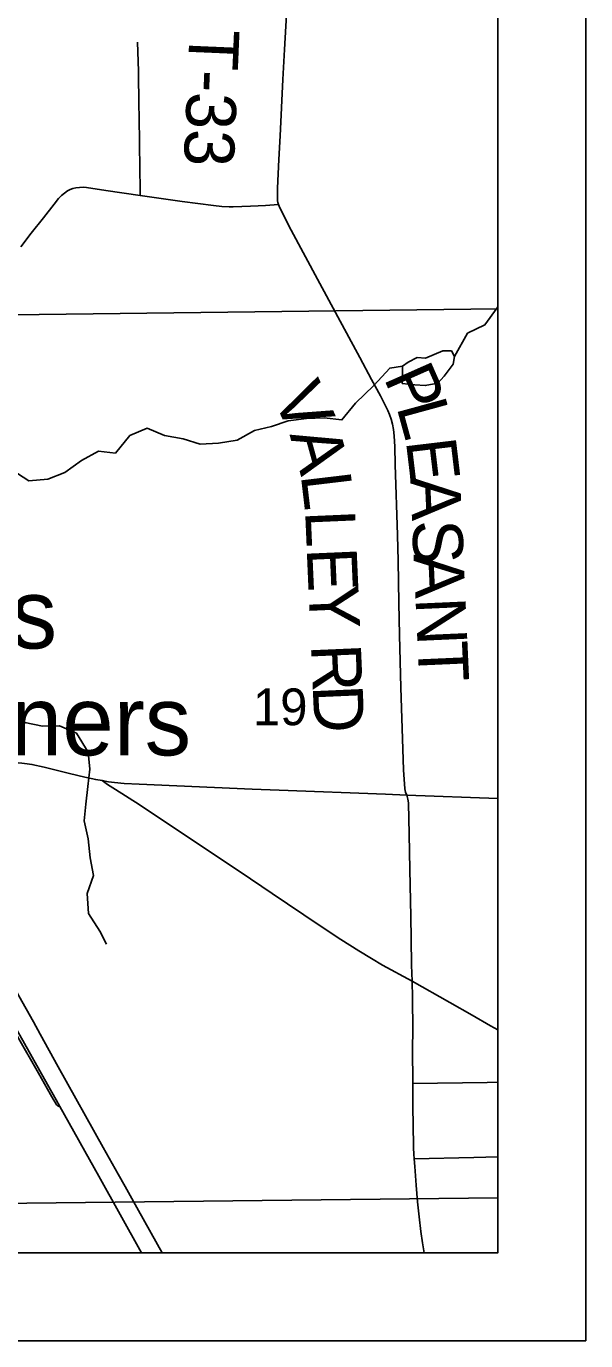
# Model space of a CAD drawing. Extents: x -6.4 to 34, y -4.2 to 22.
# Drawn here: x 8.363 to 9, y 14 to 15.496 of the extents above; entities that cross this region are included whole.
import ezdxf

# ---------------------------------------------------------------- set-up
doc = ezdxf.new("R2010")
doc.units = 0
for name, color, linetype in [('GM_X_Corporation', 7, 'Continuous'), ('GM_X_County_Road', 7, 'Continuous'), ('GM_X_Interchange_Ramps', 7, 'Continuous'), ('GM_X_Minor_Lake', 7, 'Continuous'), ('GM_X_Minor_River', 7, 'Continuous'), ('GM_X_Section_Text', 7, 'Continuous'), ('GM_X_State_Route', 7, 'Continuous'), ('GM_X_Township_Road', 7, 'Continuous'), ('GM_X_Township_Road_Text', 7, 'Continuous'), ('GM_X_Unincorporated_Text', 7, 'Continuous'), ('SH_Data', 7, 'Continuous')]:
    doc.layers.add(name, color=color, linetype=linetype)

msp = doc.modelspace()

# ---------------------------------------------------------------- linework, layer by layer
at = {"layer": 'GM_X_Corporation'}
for points in [[(8.9, 15.1746), (8.9, 15.9375), (8.744, 15.9349), (8.175, 15.9256), (8.0507, 15.9235), (8.0705, 15.1646)], [(7.1124, 14.1), (8.9, 14.1), (8.9, 15.9356), (8.6815, 15.9311), (7.2926, 15.9044), (7.2702, 15.904), (7.0636, 15.9014), (7.0744, 15.3393), (7.0897, 14.8536), (7.0948, 14.7153), (7.0983, 14.5939), (7.1017, 14.4646)], [(8.9, 14.1628), (8.9, 15.1746), (8.0705, 15.1646), (8.0954, 14.1535)], [(8.0976, 14.1), (8.9, 14.1), (8.9, 14.1628), (8.0954, 14.1535)]]:
    msp.add_lwpolyline(points, close=True, dxfattribs=at)
at = {"layer": 'GM_X_County_Road'}
for points in [[(8.3427, 14.6579), (8.3504, 14.658), (8.3544, 14.6579), (8.3583, 14.6575), (8.3646, 14.6568), (8.3698, 14.656), (8.3839, 14.6528), (8.4126, 14.6459), (8.4301, 14.6416), (8.4425, 14.6389), (8.4497, 14.6376), (8.457, 14.6363), (8.4638, 14.6354), (8.475, 14.6344), (8.4918, 14.6336), (8.6204, 14.6279), (8.6514, 14.6267), (8.7723, 14.6221)], [(8.7723, 14.6221), (8.7963, 14.6212), (8.9, 14.6174)]]:
    msp.add_lwpolyline(points, dxfattribs=at)
at = {"layer": 'GM_X_Interchange_Ramps'}
msp.add_lwpolyline([(8.3533, 14.3463), (8.3773, 14.3047), (8.391, 14.2803), (8.394, 14.2749), (8.3959, 14.2718), (8.3975, 14.2692), (8.398, 14.2686), (8.3989, 14.2677), (8.3994, 14.2673), (8.4003, 14.2669), (8.401, 14.2667), (8.4017, 14.2665)], dxfattribs=at)
at = {"layer": 'GM_X_Minor_Lake'}
msp.add_line((8.7915, 15.1022), (8.791, 15.0896), dxfattribs=at)
msp.add_lwpolyline([(8.791, 15.0896), (8.8054, 15.0881), (8.8175, 15.0873), (8.8319, 15.0902), (8.8388, 15.0982), (8.8491, 15.1118), (8.8506, 15.1205), (8.8473, 15.127), (8.8374, 15.127), (8.8177, 15.1184), (8.8082, 15.1192), (8.798, 15.1139), (8.7915, 15.1094), (8.7915, 15.1022)], dxfattribs=at)
at = {"layer": 'GM_X_Minor_River'}
for points in [[(8.8506, 15.1205), (8.8656, 15.147), (8.8853, 15.1564), (8.8994, 15.1757), (8.9, 15.1769)], [(8.3471, 14.9914), (8.3663, 14.9791), (8.3879, 14.9809), (8.4072, 14.9885), (8.4262, 15.002), (8.4456, 15.0126), (8.4649, 15.0106), (8.4813, 15.0307), (8.5011, 15.0389), (8.5207, 15.0305), (8.5419, 15.0266), (8.5612, 15.0208), (8.582, 15.0219), (8.6036, 15.0252), (8.6233, 15.0361), (8.6423, 15.0406), (8.6616, 15.0473), (8.6825, 15.0499), (8.7026, 15.0506), (8.7226, 15.0482), (8.7382, 15.0675), (8.7588, 15.0875), (8.7771, 15.1072), (8.7915, 15.1094)], [(8.362, 14.7039), (8.382, 14.6996), (8.4013, 14.6999), (8.4206, 14.6915), (8.4337, 14.6701), (8.4358, 14.6508), (8.4334, 14.631), (8.4314, 14.6109), (8.4294, 14.5919), (8.4338, 14.5714), (8.436, 14.5498), (8.44, 14.5296), (8.4327, 14.5091), (8.4341, 14.4863), (8.4472, 14.4662), (8.4547, 14.4513)]]:
    msp.add_lwpolyline(points, dxfattribs=at)
at = {"layer": 'GM_X_State_Route'}
for points in [[(8.518, 14.1), (8.491, 14.1484), (8.4758, 14.1756), (8.4679, 14.1897), (8.451, 14.2201), (8.3999, 14.3119), (8.3794, 14.3489), (8.3716, 14.363), (8.3549, 14.3926), (8.3447, 14.4114), (8.3212, 14.452), (8.3024, 14.484), (8.2867, 14.5102), (8.2637, 14.5475), (8.2428, 14.5792), (8.2101, 14.6268), (8.2013, 14.6392), (8.1947, 14.6485)], [(8.4945, 14.1), (8.446, 14.1875), (8.4017, 14.2665), (8.3976, 14.2741), (8.3875, 14.2918), (8.3526, 14.3541)]]:
    msp.add_lwpolyline(points, dxfattribs=at)
at = {"layer": 'GM_X_Township_Road'}
for points in [[(8.7963, 14.6212), (8.795, 14.6244), (8.7945, 14.6264), (8.7942, 14.6282), (8.7928, 14.6498), (8.7918, 14.6734), (8.7898, 14.7437), (8.7882, 14.8033), (8.7874, 14.84), (8.7868, 14.8878), (8.7857, 14.9169), (8.7833, 14.9977), (8.7828, 15.0176), (8.7821, 15.03), (8.7813, 15.0373), (8.7802, 15.0434), (8.7786, 15.0493), (8.7768, 15.0545), (8.7749, 15.059), (8.7664, 15.0756), (8.7564, 15.0942), (8.743, 15.1194), (8.718, 15.1658), (8.695, 15.2085), (8.665, 15.2644), (8.655, 15.2837), (8.6511, 15.2916), (8.6504, 15.2937), (8.6498, 15.2957), (8.6495, 15.2978), (8.6492, 15.3035), (8.6493, 15.3122), (8.6509, 15.3446), (8.6524, 15.3718), (8.6555, 15.4358), (8.6574, 15.4699), (8.6595, 15.5097)], [(8.493, 15.3038), (8.4929, 15.31), (8.4924, 15.3615), (8.4918, 15.395), (8.4916, 15.4055), (8.491, 15.4452), (8.4902, 15.4782)], [(8.3574, 15.2455), (8.3692, 15.2607), (8.3829, 15.2784), (8.3951, 15.294), (8.4003, 15.3002), (8.4037, 15.3037), (8.4068, 15.3066), (8.4103, 15.309), (8.4135, 15.3106), (8.4163, 15.3116), (8.4199, 15.3125), (8.4241, 15.313), (8.4283, 15.3131), (8.432, 15.3129), (8.454, 15.3096), (8.493, 15.3038), (8.5407, 15.2969), (8.5765, 15.2922), (8.5858, 15.2913), (8.5945, 15.291), (8.5989, 15.291), (8.6185, 15.2916), (8.6275, 15.2919), (8.6355, 15.2923), (8.6504, 15.2937)], [(8.4497, 14.6376), (8.456, 14.6331), (8.465, 14.6274), (8.4919, 14.6104), (8.5675, 14.5601), (8.6067, 14.5338), (8.6433, 14.5091), (8.6969, 14.4729), (8.7213, 14.4568), (8.7417, 14.4438), (8.7561, 14.4352), (8.7689, 14.4277), (8.8025, 14.4092)], [(8.8161, 14.1), (8.8144, 14.1114), (8.8125, 14.1243), (8.8105, 14.1409), (8.8086, 14.158), (8.807, 14.1769), (8.8054, 14.1985), (8.8049, 14.207), (8.8046, 14.2122), (8.8042, 14.2196), (8.8039, 14.2314), (8.8038, 14.2357), (8.8036, 14.2519), (8.8034, 14.2599), (8.8033, 14.2928), (8.8031, 14.3326), (8.8033, 14.3537), (8.8031, 14.3904), (8.8025, 14.4092), (8.8019, 14.4276), (8.8014, 14.4575), (8.8009, 14.483), (8.7999, 14.5364), (8.7991, 14.5768), (8.7984, 14.6121), (8.7981, 14.6145), (8.7977, 14.6166), (8.7963, 14.6212)], [(8.8025, 14.4092), (8.8455, 14.3852), (8.8708, 14.3706), (8.8917, 14.3584), (8.9, 14.3538)], [(8.8033, 14.2928), (8.8877, 14.2941), (8.9, 14.2945)], [(8.8049, 14.207), (8.8729, 14.2085), (8.9, 14.2092)]]:
    msp.add_lwpolyline(points, dxfattribs=at)
at = {"layer": 'SH_Data'}
for p, q in [((9, 21), (9, 14)), ((8.9, 20.9), (8.9, 14.1)), ((2.1, 14.1), (8.9, 14.1)), ((2, 14), (9, 14))]:
    msp.add_line(p, q, dxfattribs=at)

# ---------------------------------------------------------------- texts
at = {"layer": 'GM_X_Section_Text'}
msp.add_text('19', height=0.04186, rotation=0, dxfattribs=at).set_placement((8.6212, 14.7007))
at = {"layer": 'GM_X_Township_Road_Text'}
for s, height, rotation, p in [('T-33', 0.05682, 267.5258, (8.5494, 15.494)), ('P', 0.0568, 293.8623, (8.7697, 15.0963)), ('V', 0.0568, 294.028, (8.6433, 15.0753)), ('L', 0.0568, 285.3352, (8.7845, 15.0634)), ('A', 0.0568, 285.4149, (8.6629, 15.0317)), ('E', 0.0568, 276.8082, (8.7953, 15.0246)), ('L', 0.0568, 276.8018, (8.6757, 14.9857)), ('A', 0.0568, 272.5446, (8.8002, 14.9835)), ('L', 0.0568, 272.4953, (8.6807, 14.9447)), ('S', 0.0568, 272.5446, (8.8024, 14.9335)), ('E', 0.0568, 272.4953, (8.6825, 14.9022)), ('A', 0.0568, 272.5446, (8.8041, 14.8952)), ('Y', 0.0568, 272.4953, (8.6844, 14.8597)), ('N', 0.0568, 272.5446, (8.8063, 14.8453)), ('R', 0.0568, 272.4953, (8.6873, 14.7923)), ('T', 0.0568, 272.5446, (8.8086, 14.7953)), ('D', 0.0568, 272.4953, (8.6893, 14.7457))]:
    msp.add_text(s, height=height, rotation=rotation, dxfattribs=at).set_placement(p)
at = {"layer": 'GM_X_Unincorporated_Text'}
for s, p in [('Loys', (8.1754, 14.7881)), ('Corners', (8.1754, 14.6664))]:
    msp.add_text(s, height=0.07898, rotation=0, dxfattribs=at).set_placement(p)

doc.saveas('drawing.dxf')
